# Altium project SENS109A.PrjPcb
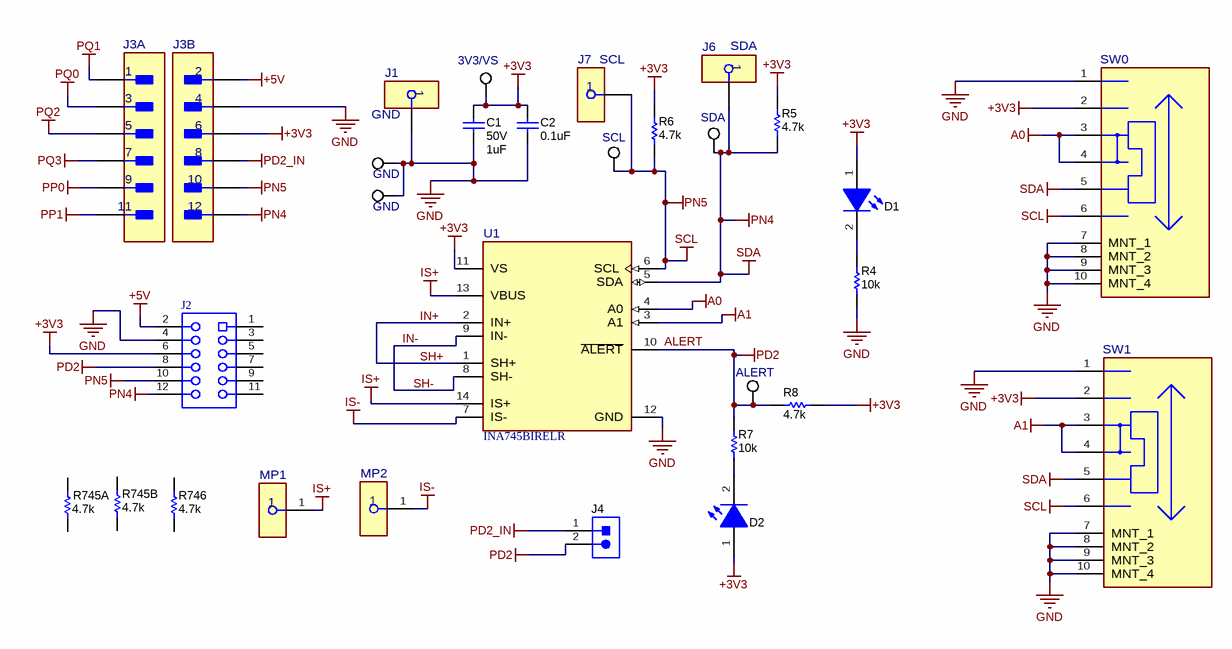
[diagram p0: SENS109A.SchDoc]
TID: N/A; TechSupport: http://www.ti.com/support; SCH_Rev: A; PRJ_Title: INA745-INA746EVM; PRJ_Number: SENS109; PRJ_Customer: Public Release; PCB_Rev: A; CopyrightYear: 2023
2 sheets, 50 parts. Net scope: global (net labels, ports and power ports of the same name join across sheets).
Board file: SENS109A.PcbDoc
Sheets:
  SENS109A.SchDoc
  SENS109A_HW.SchDoc

## Sheet SENS109A.SchDoc
size 431 x 279 mm; Date: Not shown in title block; ApprovedBy: Not shown in title block; CheckedBy: Not shown in title block; Author: Not shown in title block; CompanyName: Not shown in title block; Engineer: Not shown in title block; Organization: Not shown in title block; Address1: Not shown in title block; Address2: Not shown in title block; Address3: Not shown in title block; Address4: Not shown in title block; DocumentNumber: 2; Revision: Use project parameter SCH_Rev; SheetNumber: 2; SheetTotal: 3; PageSetup: Record=PageOptions¦CenterHorizontal=True¦CenterVertical=True¦PrintScale=1.00¦XCorrection=1.00¦YCorrection=1.00¦PrintKind=0¦BorderSize=5000000¦LeftOffset=0¦BottomOffset=0¦Orientation=2¦PaperLength=1000¦PaperWidth=1000¦Scale=100¦PaperSource=15¦PrintQuality=600¦MediaType=1¦DitherType=10¦PaperKind=Letter¦PrintScaleMode=1

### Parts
C1  VDC_V: 50V  ValueDisplayed: 1uF  [0603]  (hidden comment: C1608X6S1H105K080AC)
C2  ValueDisplayed: 0.1uF  [0402]  (hidden comment: GRM155R71H104ME14D)
D1  POWER  [VAOL-0805_White]  (value not drawn)
D2  ALERT  [VAOL-0805_White]  (value not drawn)
J1  GND  [FP-3-331272-8_PIN_RCPT-MFG]
J2  NPPN062FJFN-RC  [Sullins_NPxN062FJFN]  (value not drawn)
J3  NRPN062PARN-RC  [FP-NRPN062PARN-RC_HDR12-MFG]  (value not drawn)  (parts A,B of 2)
J4  ALERT BUS  [WURTH_61300211121]  (value not drawn)
J6  SDA  [FP-3-331272-8_PIN_RCPT-MFG]
J7  SCL  [FP-3-331272-8_PIN_RCPT-MFG]
MP1  CB70-14-CY  [FP-LAMA6-14-QY_TERMINAL_CONN-MFG]  (value not drawn)
MP2  CB70-14-CY  [FP-LAMA6-14-QY_TERMINAL_CONN-MFG]  (value not drawn)
R4  ValueDisplayed: 10k  [0603]  (hidden comment: CRCW060310K0JNEA)
R5  ValueDisplayed: 4.7k  [0603]  (hidden comment: CRCW06034K70JNEA)
R6  ValueDisplayed: 4.7k  [0603]  (hidden comment: CRCW06034K70JNEA)
R7  ValueDisplayed: 10k  [0603]  (hidden comment: CRCW060310K0JNEA)
R8  ValueDisplayed: 4.7k  [0603]  (hidden comment: CRCW06034K70JNEA)
R745A  ValueDisplayed: 4.7k  [0603]  (hidden comment: INA745A)
R745B  ValueDisplayed: 4.7k  [0603]  (hidden comment: INA745B)
R746  ValueDisplayed: 4.7k  [0603]  (hidden comment: INA746)
SW0  CUS-14TB  [FP-CUS-14TB_SMT_SW_11MM3_4MM1-MFG]  (value not drawn)
SW1  CUS-14TB  [FP-CUS-14TB_SMT_SW_11MM3_4MM1-MFG]  (value not drawn)
TP3  3V3/VS  [Testpoint_Keystone_Miniature]
TP4  GND  [Testpoint_Keystone_Miniature]
TP5  GND  [Testpoint_Keystone_Miniature]
TP7  SDA  [Testpoint_Keystone_Miniature]
TP8  SCL  [Testpoint_Keystone_Miniature]
TP11  ALERT  [Testpoint_Keystone_Miniature]
U1  INA745BIRELR  [REL0014B-MFG]

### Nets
+3V3: C1.1 C2.1 D1.1(A) D2.1(A) J2.6 J3.6 R5.2 R6.2 R8.2 SW0.2 SW1.2 TP3.1 U1.11(VS)
+5V: J2.2 J3.2
A0: SW0.3(C) SW0.4(C) U1.4(A0)
A1: SW1.3(C) SW1.4(C) U1.3(A1)
ALERT: J2.8 J4.2 R7.1 R8.1 TP11.1 U1.10(~{ALERT})  [also labelled PD2]
GND: C1.2 C2.2 J1.1 J2.4 J3.4 R4.1 SW0.1 SW0.7(MNT_1) SW0.8(MNT_2) SW0.9(MNT_3) SW0.10(MNT_4) SW1.1 SW1.7(MNT_1) SW1.8(MNT_2) SW1.9(MNT_3) SW1.10(MNT_4) TP4.1 TP5.1 U1.12(GND)
IS+: MP1.1 U1.13(VBUS) U1.14(IS+)
IS-: MP2.1 U1.7(IS-)
PD2_IN: J3.8 J4.1
PN4: J2.12 J3.12 J6.1 R5.1 SW0.5 SW1.5 TP7.1 U1.5(SDA)  [also labelled SDA]
PN5: J2.10 J3.10 J7.1 R6.1 SW0.6 SW1.6 TP8.1 U1.6(SCL)  [also labelled SCL]
PP0: J3.9
PP1: J3.11
PQ0: J3.3
PQ1: J3.1
PQ2: J3.5
PQ3: J3.7
NetD1_2: D1.2(K) R4.2
NetD2_2: D2.2(K) R7.2
NetU1_1: U1.1(SH+) U1.2(IN+)
NetU1_8: U1.8(SH-) U1.9(IN-)

Not connected (* = marked no-connect by the designer): J2 1 3 5 7 9 11; R745A 1 2; R745B 1 2; R746 1 2

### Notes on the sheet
- Labels drawn without touching a wire or pin: IN+, IN-, SH+, SH-

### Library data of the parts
C1 = CMP-0007029-4: CAP, CERM, 1 uF, 50 V, +/- 10%, X6S, 0603; Manufacturer: TDK; TaMin_C: -55°C; ESR_ohm: 5.522m; Polarized: N; SizeAreaWB_mm2: 4.68; Value1: 0.005522 ohm; U/M: EA; Value: 1uF; TaMax_C: 105°C; SizeZ_mm: 1; SizeX_mm: 1.6; SizeY_mm: 0.8; SizeArea_mm2: 1.28; Cap_F: 1µF; IRMS_A: 2.21617A; AEC Category: Q200
C2 = CMP-0006675-2: CAP, CERM, 0.1 uF, 50 V, +/- 20%, X7R, 0402; Manufacturer: MuRata; Polarized: N; Value: 0.1uF; U/M: EA; Cap_F: 100nF; Value1: Unknown; VDC_V: 50V; TaMin_C: -55°C; TaMax_C: 125°C; SizeArea_mm2: 0.5; SizeAreaWB_mm2: 3; SizeX_mm: 1; SizeZ_mm: 0.6; AEC Category: Q200
D1 D2 = CMP-0002885-2: LED, White, SMD; PartNumber: VAOL-S8WR4; Manufacturer: Visual Communications Company, LLC; Type: InGaN; Value1: W; Io_A: 5mA; Vf_V: 2.925V
J1 J6 J7 = CMP-0086763-1: CONN PIN RCPT .018-.021 SOLDER; PartNumber: 3-331272-8; Manufacturer: TE Connectivity; ContactFinish: Gold,Nickel; Current_A: 5A
J2 = CMP-0054670-1: Receptacle, 2mm, 6x2, Gold, R/A, TH; Manufacturer: Sullins Connector Solutions; CNHeader: FALSE; Gender: Female; CompType: Socket Strip; Row_Count: 2; CT: TRUE
J3 = CMP-0090321-1: CONN HEADER R/A 12POS 2MM; Manufacturer: Sullins Connector Solutions; Voltage_V: 150V; Row_Count: 2; Conn Gender: Male; AEC Qualified: No; SizeZ_mm: 4.2mm; Conn Orientation: Right Angle; ContactFinish: Gold; Current_A: 2A
J4 = CMP-0054794-2: Header, 2.54 mm, 2x1, Gold, TH; Manufacturer: Wurth Elektronik; PartNumber: 61300211121; Shrouded: N; Gender: Male; Green_REACh: Passed; Pitch_mm: 2.54; Green_Lifecycle: Active; Row_Count: 1; Cert_UL: Y
MP1 MP2 = CMP-0091352-2: Terminal Connector Rectangular Lug, 1/4 Stud; Manufacturer: Panduit; SizeZ_mm: 0.54inch; AEC Qualified: No; Is Female: yes
R4 R7 = CMP-0025701-3: RES, 10 k, 5%, 0.1 W, 0603; Manufacturer: Vishay-Dale; Power_W: 100mW; TempCo: 200 ppm/C; Value_Code: 10k0; U/M: EA; Value: 10k; EIA_Code: E24; SizeX_mm: 1.6; SizeY_mm: 0.8; SizeZ_mm: 1; Value2: 0.1W; SizeArea_mm2: 1.28; VDC_V: 75V; AEC Category: Q200
R5 R6 R8 = CMP-0025817-3: RES, 4.7 k, 5%, 0.1 W, 0603; Manufacturer: Vishay-Dale; Power_W: 100mW; TempCo: 200 ppm/C; Value_Code: 4k70; U/M: EA; Value: 4.7k; EIA_Code: E24; SizeX_mm: 1.6; SizeY_mm: 0.8; SizeZ_mm: 1; Value2: 0.1W; SizeArea_mm2: 1.28; VDC_V: 75V; AEC Category: Q200
R745A R745B R746 = CMP-0025817-3: RES, 4.7 k, 5%, 0.1 W, 0603; Manufacturer: Vishay-Dale; PartNumber: CRCW06034K70JNEA; Power_W: 100mW; TempCo: 200 ppm/C; Value_Code: 4k70; U/M: EA; Value: 4.7k; EIA_Code: E24; SizeX_mm: 1.6; SizeY_mm: 0.8; SizeZ_mm: 1; Value2: 0.1W; SizeArea_mm2: 1.28; VDC_V: 75V; AEC Category: Q200
SW0 SW1 = CMP-0088487-2: Slide Switch SP4T Surface Mount, Right Angle; Manufacturer: Nidec Copal Electronics; Operating Force: 1.5/2/2/1.5/2/2N; AEC Qualified: No; VDC_V: 50V; Electromechanical Life: 10000Cycles; Coil Resistance_ohm: 70mΩ; Contact Current Rating: 300mA; SizeZ_mm: 1.6mm
TP3-TP5 TP7 TP8 TP11 = CMP-0055152-1: Test Point, Miniature, SMT; Manufacturer: Keystone; CNHeader: FALSE; Green_Lifecycle: Active; Green_REACh: Passed; CT: TRUE
U1 = CMP-0096083-1: 40-V, Integrated Sense Element, 16-Bit, Precision Power/Energy/Charge Monitor With I 2C Interface; Manufacturer: Texas Instruments; Standoff Height: 0mm; AEC Qualified: No; SizeZ_mm: 1mm; Nominal Supply Current: 640uA; TJmax_C: +165°C; TaMax_C: +125°C; Max Supply Voltage: 5.5V; TaMin_C: -40°C; Min Supply Voltage: 2.7V

## Sheet SENS109A_HW.SchDoc
size 431 x 279 mm; Date: Not shown in title block; ApprovedBy: Not shown in title block; CheckedBy: Not shown in title block; Author: Not shown in title block; CompanyName: Not shown in title block; Engineer: Not shown in title block; Organization: Not shown in title block; Address1: Not shown in title block; Address2: Not shown in title block; Address3: Not shown in title block; Address4: Not shown in title block; DocumentNumber: 3; Revision: Use project parameter SCH_Rev; SheetNumber: 3; SheetTotal: 3; PageSetup: Record=PageOptions¦CenterHorizontal=True¦CenterVertical=True¦PrintScale=1.00¦XCorrection=1.00¦YCorrection=1.00¦PrintKind=0¦BorderSize=5000000¦LeftOffset=0¦BottomOffset=0¦Orientation=2¦PaperLength=1000¦PaperWidth=1000¦Scale=100¦PaperSource=15¦PrintQuality=600¦MediaType=1¦DitherType=10¦PaperKind=Letter¦PrintScaleMode=1
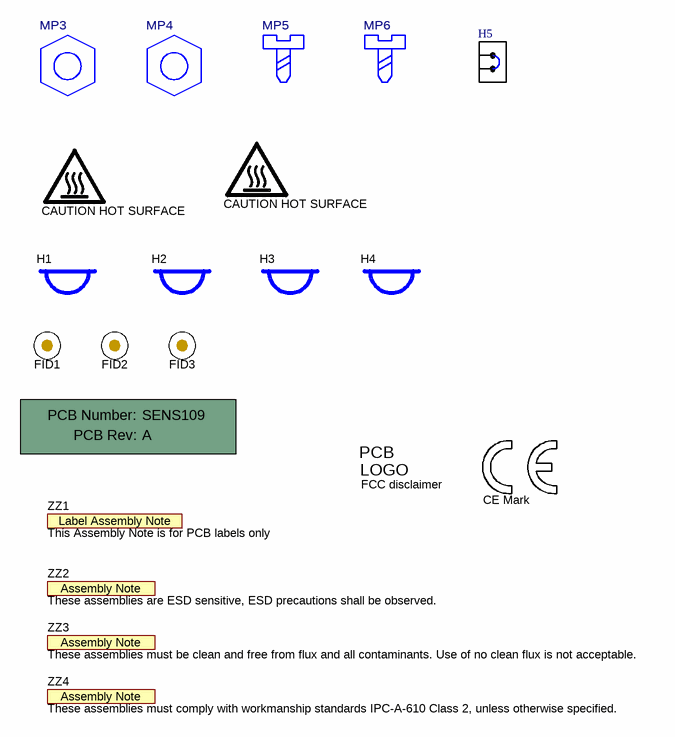
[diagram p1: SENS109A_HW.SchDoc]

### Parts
!PCB1  Printed Circuit Board  (value not drawn)  (mechanical)
FID1  Fiducial  [Fiducial10-20]  (value not drawn)
FID2  Fiducial  [Fiducial10-20]  (value not drawn)
FID3  Fiducial  [Fiducial10-20]  (value not drawn)
H1  SJ61A2  [Bumpon_SJ61A2]  (value not drawn)
H2  SJ61A2  [Bumpon_SJ61A2]  (value not drawn)
H3  SJ61A2  [Bumpon_SJ61A2]  (value not drawn)
H4  SJ61A2  [Bumpon_SJ61A2]  (value not drawn)
H5  60900213421  [Wurth_60900213421]  (value not drawn)
Logo2  CAUTION HOT SURFACE  [IEC_HotSurface_Medium]  (no BOM)
Logo3  FCC disclaimer  [FCC_disclaimer]  (no BOM)
LOGO4  CE Mark  [CE_Mark_5mm]  (no BOM)
Logo5  CAUTION HOT SURFACE  [IEC_HotSurface_Medium]  (no BOM)
MP3  95462A029  [FP-95462A029_NUT_1-4-20-MFG]  (value not drawn)
MP4  95462A029  [FP-95462A029_NUT_1-4-20-MFG]  (value not drawn)
MP5  91735A535  [FP-90283A537-MFG]  (value not drawn)
MP6  91735A535  [FP-90283A537-MFG]  (value not drawn)
ZZ1  This Assembly Note is for PCB labels only  [AssemblyNoteLabel]  (no BOM)
ZZ2  These assemblies are ESD sensitive, ESD precautions shall be observed.  [AssemblyNote]  (no BOM)
ZZ3  These assemblies must be clean and free from flux and all contaminants. Use of no clean flux is not acceptable.  [AssemblyNote]  (no BOM)
ZZ4  These assemblies must comply with workmanship standards IPC-A-610 Class 2, unless otherwise specified.  [AssemblyNote]  (no BOM)

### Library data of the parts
!PCB1 = CMP-0003618-2: Manufacturer: Any; PartNumber: SENS109
FID1-FID3 = CMP-0077181-1: Fiducial mark.  There is nothing to buy or mount.
H1-H4 = CMP-0003622-1: Bumpon, Hemisphere, 0.375 X 0.235, Black; Manufacturer: 3M
H5 = CMP-0003761-2: Shunt, 2.54mm, Gold, Black; Manufacturer: Wurth Elektronik
Logo2 Logo5 = CMP-0074837-2: IEC 61010-1 Hot Surface Warning; Manufacturer: Texas Instruments; CompType: IC; AEC Category: Q200; SymbolCreator: a0412235
Logo3 = CMP-0074847-1: FCC_disclaimer
LOGO4 = CMP-0074844-1: SymbolCreator: a0412235
MP3 MP4 = CMP-0088009-1: Medium-Strength Steel Hex Nut; Manufacturer: McMASTER-CARR
MP5 MP6 = CMP-0088011-2: Pan Head Phillips Screw 1/4"-20, 3/8" Long; Manufacturer: McMaster-CARR
ZZ1 = CMP-0003616-3
ZZ2 = CMP-0077236-1
ZZ3 = CMP-0077237-1
ZZ4 = CMP-0077238-1

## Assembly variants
001: not fitted C1 FID1 FID2 FID3 J1 J6 J7 R745B R746; alternate parts U1 -> CMP-0035136-1
002: not fitted C1 FID1 FID2 FID3 J1 J6 J7 R745A R746
003: not fitted C1 FID1 FID2 FID3 J1 J6 J7 R745A R745B; alternate parts U1 -> CMP-0035137-1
